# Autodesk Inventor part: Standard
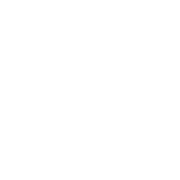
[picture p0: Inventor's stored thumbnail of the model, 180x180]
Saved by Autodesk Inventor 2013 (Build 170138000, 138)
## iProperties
Created: 2005-05
Part Number: Standard
Document SubType Name: Modeling
Designer: JWe
Density: 1 g/cm^3
Material: Generic
Author: JWe
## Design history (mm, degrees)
